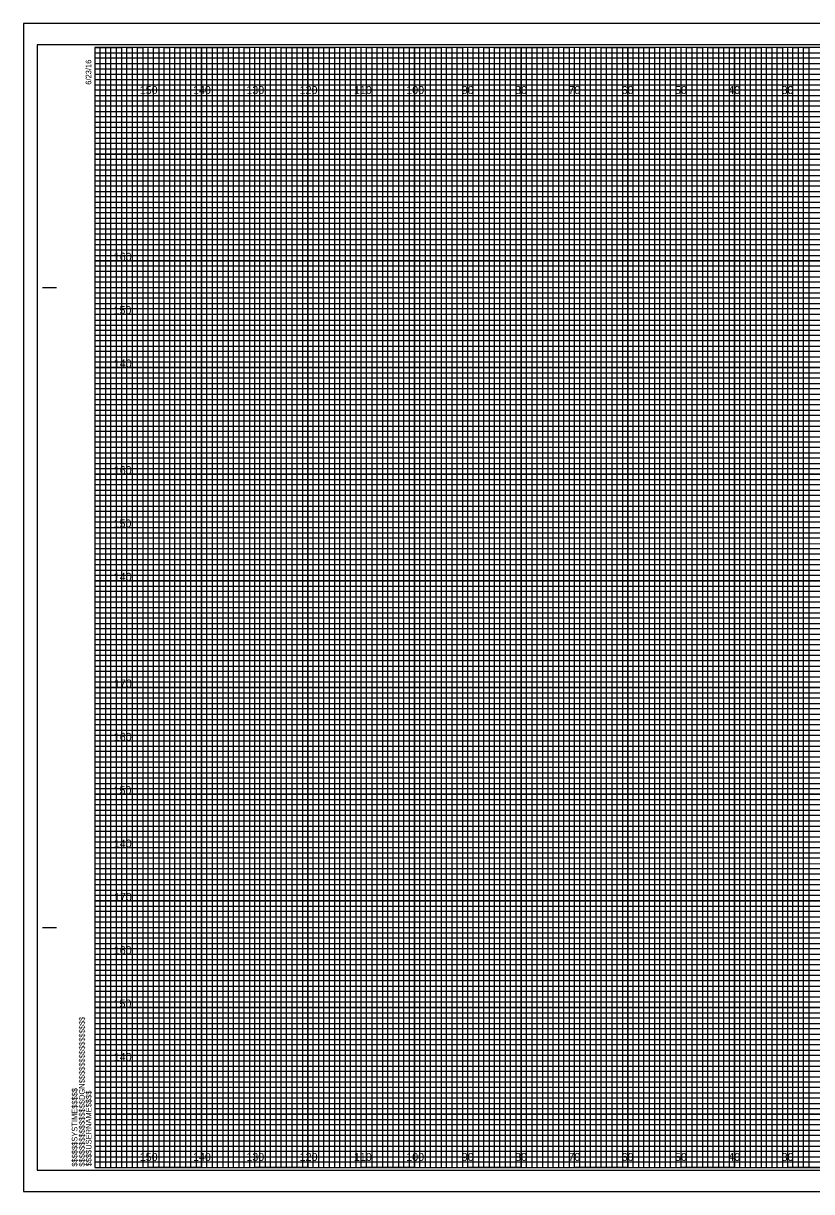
# Model space of a CAD drawing. Extents: x -13 to 323, y -5 to 434.
# Drawn here: x -13.4 to 134.5, y -4.5 to 214.5 of the extents above; entities that cross this region are included whole.
import ezdxf

# ---------------------------------------------------------------- set-up
doc = ezdxf.new("R2010")
doc.units = 0
for name, color, linetype in [('Exist Cross Section Cell', 7, 'Continuous'), ('Exist XS Center Line Elevation Label', 7, 'Continuous'), ('Exist XS Ground Line', 7, 'Continuous'), ('Prop CMT Pvmt Course 1', 7, 'Continuous'), ('Prop CMT Pvmt Course 3', 7, 'Continuous'), ('Prop CMT Pvmt Surface', 7, 'Continuous'), ('Prop CMT Pvmt Surface Shoulder', 7, 'Continuous'), ('Prop CMT Shld Paved Course 1', 7, 'Continuous'), ('Prop CMT Shld Paved Course 2', 7, 'Continuous'), ('Prop CMT Shld Paved Course 3', 7, 'Continuous'), ('Prop CMT Subgrade Earthwork', 7, 'Continuous')]:
    doc.layers.add(name, color=color, linetype=linetype)

msp = doc.modelspace()

# ---------------------------------------------------------------- linework, layer by layer
at = {"layer": 'Exist XS Center Line Elevation Label'}
for points in [[(0, 210), (5, 210), (5, 0), (15, 0), (15, 210), (25, 210), (25, 0), (35, 0), (35, 210), (45, 210), (45, 0), (55, 0), (55, 210), (65, 210), (65, 0), (75, 0), (75, 210), (85, 210), (85, 0), (95, 0), (95, 210), (105, 210), (105, 0), (115, 0), (115, 210), (125, 210), (125, 0), (135, 0)], [(0, 205), (275, 205)], [(0, 185), (320, 185), (320, 195), (0, 195)], [(0, 165), (320, 165), (320, 175), (0, 175)], [(0, 145), (320, 145), (320, 155), (0, 155)], [(0, 125), (320, 125), (320, 135), (0, 135)], [(0, 105), (320, 105), (320, 115), (0, 115)], [(0, 85), (320, 85), (320, 95), (0, 95)], [(0, 65), (320, 65), (320, 75), (0, 75)], [(0, 45), (320, 45), (320, 55), (0, 55)], [(0, 25), (320, 25), (320, 35), (0, 35)], [(0, 5), (320, 5), (320, 15), (0, 15)]]:
    msp.add_lwpolyline(points, dxfattribs=at)
at = {"layer": 'Exist XS Ground Line'}
for p, q in [((10, 210), (0, 210)), ((10, 0), (10, 210)), ((30, 210), (20, 210)), ((20, 210), (20, 0)), ((30, 0), (30, 210)), ((50, 210), (40, 210)), ((40, 210), (40, 0)), ((50, 0), (50, 210)), ((70, 210), (60, 210)), ((60, 210), (60, 0)), ((70, 0), (70, 210)), ((90, 210), (80, 210)), ((80, 210), (80, 0)), ((90, 0), (90, 210)), ((110, 210), (100, 210)), ((100, 210), (100, 0)), ((110, 0), (110, 210)), ((130, 210), (120, 210)), ((120, 210), (120, 0)), ((130, 0), (130, 210)), ((20, 0), (10, 0)), ((40, 0), (30, 0)), ((60, 0), (50, 0)), ((80, 0), (70, 0)), ((100, 0), (90, 0)), ((120, 0), (110, 0)), ((140, 0), (130, 0))]:
    msp.add_line(p, q, dxfattribs=at)
for points in [[(0, 200), (320, 200), (320, 190), (0, 190)], [(0, 180), (320, 180), (320, 170), (0, 170)], [(0, 160), (320, 160), (320, 150), (0, 150)], [(0, 140), (320, 140), (320, 130), (0, 130)], [(0, 120), (320, 120), (320, 110), (0, 110)], [(0, 100), (320, 100), (320, 90), (0, 90)], [(0, 80), (320, 80), (320, 70), (0, 70)], [(0, 60), (320, 60), (320, 50), (0, 50)], [(0, 40), (320, 40), (320, 30), (0, 30)], [(0, 20), (320, 20), (320, 10), (0, 10)]]:
    msp.add_lwpolyline(points, dxfattribs=at)
at = {"layer": 'Prop CMT Pvmt Course 3'}
msp.add_lwpolyline([(-13.4, -4.5), (323.3, -4.5), (323.3, 214.5), (-13.4, 214.5)], close=True, dxfattribs=at)
at = {"layer": 'Prop CMT Pvmt Surface'}
for p, q in [((10, 0), (10, 210)), ((20, 0), (20, 210)), ((30, 0), (30, 210)), ((40, 0), (40, 210)), ((50, 0), (50, 210)), ((60, 0), (60, 210)), ((70, 0), (70, 210)), ((80, 0), (80, 210)), ((90, 0), (90, 210)), ((100, 0), (100, 210)), ((110, 0), (110, 210)), ((120, 0), (120, 210)), ((130, 0), (130, 210)), ((0, 200), (320, 200)), ((0, 190), (320, 190)), ((0, 180), (320, 180)), ((0, 170), (320, 170)), ((0, 160), (320, 160)), ((0, 150), (320, 150)), ((0, 140), (320, 140)), ((0, 130), (320, 130)), ((0, 120), (320, 120)), ((0, 110), (320, 110)), ((0, 100), (320, 100)), ((0, 90), (320, 90)), ((0, 80), (320, 80)), ((0, 70), (320, 70)), ((0, 60), (320, 60)), ((0, 50), (320, 50)), ((0, 40), (320, 40)), ((0, 30), (320, 30)), ((0, 20), (320, 20)), ((0, 10), (320, 10))]:
    msp.add_line(p, q, dxfattribs=at)
at = {"layer": 'Prop CMT Pvmt Surface Shoulder'}
for p, q in [((323.3, 214.5), (-13.4, 214.5)), ((-13.4, 214.5), (-13.4, -4.5)), ((-13.4, -4.5), (323.3, -4.5))]:
    msp.add_line(p, q, dxfattribs=at)
at = {"layer": 'Prop CMT Shld Paved Course 1'}
for p, q in [((0, 209), (260, 209)), ((260, 207.98), (0, 207.98)), ((0, 207.98), (0, 207)), ((0, 207), (260, 207)), ((260, 205.89), (0, 205.89)), ((0, 205.89), (0, 204)), ((0, 204), (320, 204))]:
    msp.add_line(p, q, dxfattribs=at)
for points in [[(0, 203), (270, 203), (320, 203), (320, 202), (0, 202)], [(0, 201), (320, 201), (320, 199), (0, 199)], [(0, 198), (320, 198), (320, 197), (0, 196.98)], [(0, 196), (320, 196), (320, 194), (0, 194)], [(0, 193), (320, 193), (320, 192), (0, 192)], [(0, 191), (320, 191), (320, 189), (0, 189)], [(0, 188), (320, 188), (320, 187), (0, 187)], [(0, 186), (320, 186), (320, 184), (0, 184)], [(0, 183), (320, 183), (320, 182), (0, 182)], [(0, 181), (320, 181), (320, 179), (0, 179)], [(0, 178), (320, 178), (320, 177), (0, 177)], [(0, 176), (320, 176), (320, 173.95), (320, 173), (320, 172), (0, 172)], [(0, 174), (320, 174), (320, 173), (0, 173)], [(0, 171), (320, 171), (320, 169), (0, 169.03)], [(0, 169.03), (320, 169), (320, 168), (0, 168)], [(0, 167), (320, 167), (320, 166), (0, 166)], [(0, 164), (320, 164), (320, 163), (0, 163)], [(0, 162), (320, 162), (320, 161), (0, 161)], [(-0.07, 158.89), (320, 158.89), (320, 157.88), (-0.07, 157.88)], [(0, 157), (320, 157), (320, 156), (0, 156)], [(0, 154), (320, 154), (320, 153), (0, 153)], [(0, 152), (320, 152), (320, 151), (0, 151)], [(0, 149), (320, 149), (320, 148), (0, 148)], [(0, 147), (320, 147), (320, 146), (0, 146)], [(0, 144), (320, 144), (320, 143), (0, 143)], [(0, 142), (320, 142), (320, 141), (0, 141)], [(0, 139), (320, 139), (319.99, 137.98), (0, 138)], [(0, 137), (320, 137), (320, 136), (0, 136)], [(0, 134), (320, 134), (320, 133), (0, 133)], [(0, 132), (320, 132), (320, 131), (0, 131)], [(0, 129), (320, 129), (320, 128), (0, 128)], [(0, 127), (320, 127), (320, 126), (0, 126)], [(0, 124), (320, 124), (320, 123), (0, 123)], [(0, 122), (320, 122), (320, 121), (0, 121)], [(0, 119), (320, 119), (320, 118), (0, 118)], [(0, 116.99), (320.07, 116.91), (320, 116), (0, 116)], [(0, 114), (320, 114), (320, 113), (0, 113)], [(0, 112), (320, 112), (320, 111), (0, 111)], [(0, 109), (320, 109), (320, 108), (0, 108)], [(0, 107), (320, 107), (320, 106), (0, 106)], [(0, 104), (320, 104), (320, 103), (0, 103)], [(0, 102), (320, 102), (320, 101), (0, 101)], [(0, 99), (320, 99), (320, 98), (0, 98)], [(0, 97), (320, 97), (320, 96), (0, 96)], [(0, 94), (320, 94), (320, 93), (0, 93)], [(0, 92), (320, 92), (320, 91), (0, 91)], [(0, 89), (320, 89), (320, 88), (0, 88)], [(0, 87), (320, 87), (320, 86), (0, 86)], [(0, 84), (320, 84), (320, 83), (0, 83)], [(0, 82), (320, 82), (320, 81), (0, 81)], [(0, 79), (320, 79), (319.99, 77.98), (0, 78)], [(0, 77), (320, 77), (320, 76), (0, 76)], [(0, 74), (320, 74), (320, 73), (0, 73)], [(0, 72), (320, 72), (320, 71), (0, 71)], [(0, 69), (320, 69), (320, 68), (0, 68)], [(0, 67), (320, 67), (320, 66), (0, 66)], [(0, 64), (320, 64), (320, 63), (0, 63)], [(0, 62), (320, 62), (320, 61), (0, 61)], [(0, 59), (320, 59), (320, 58), (0, 58)], [(0, 56.99), (320.07, 56.91), (320, 56), (0, 56)], [(0, 54), (320, 54), (320, 53), (0, 53)], [(0, 52), (320, 52), (320, 51), (0, 51)], [(0, 49), (320, 49), (320, 48), (0, 48)], [(0, 47), (320, 47), (320, 46), (0, 46)], [(0, 44), (320, 44), (320, 43), (0, 43)], [(0, 42), (320, 42), (320, 41), (0, 41)], [(0, 39), (320, 39), (320, 38), (0, 38)], [(0, 37), (320, 37), (320, 36), (0, 36)], [(0, 34), (320, 34), (320, 33), (0, 33)], [(0, 32), (320, 32), (320, 31), (0, 31)], [(0, 29), (320, 29), (320, 28), (0, 28)], [(0, 27), (320, 27), (320, 26), (0, 26)], [(0, 24), (320, 24), (320, 23), (0, 23)], [(0, 22), (320, 22), (320, 21), (0, 21)], [(0, 19), (320, 19), (320, 18), (0, 18)], [(0, 17), (320, 17), (320, 16), (0, 16)], [(0, 14), (320, 14), (320, 13), (0, 13)], [(0, 12), (320, 12), (320, 11), (0, 11)], [(0, 9), (320, 9), (320, 8), (0, 8)], [(0, 7), (320, 7), (320, 6), (0, 6)], [(0, 4), (320, 4), (320, 3), (0, 3)], [(0, 2), (320, 2), (320, 1), (0, 1)]]:
    msp.add_lwpolyline(points, dxfattribs=at)
at = {"layer": 'Prop CMT Shld Paved Course 2'}
for p, q in [((-9.8, 165), (-7.3, 165)), ((-9.7, 165), (-7.2, 165)), ((-9.8, 45), (-7.3, 45)), ((-9.7, 45), (-7.2, 45)), ((0, 0), (0, 0)), ((0, 0), (0, 0)), ((0, 0), (0, 0)), ((0, 0), (0, 0)), ((0, 0), (0, 0)), ((0, 0), (0, 0)), ((0, 0), (0, 0))]:
    msp.add_line(p, q, dxfattribs=at)
msp.add_lwpolyline([(320, 210), (0, 210), (0, 0), (320, 0)], close=True, dxfattribs=at)
at = {"layer": 'Prop CMT Shld Paved Course 3'}
for points in [[(0, 0), (1, 0), (1, 210), (2, 210), (2, 0)], [(2, 0), (3, 0), (3, 210), (4, 210), (4, 0)], [(5, 0), (6, 0), (6, 210), (7, 210), (7, 0)], [(7, 0), (8, 0), (8, 210), (9, 210), (9, 0)], [(10, 0), (11, 0), (11, 210), (12, 210), (12, 0)], [(12, 0), (13, 0), (13, 210), (14, 210), (14, 0)], [(15, 0), (16, 0), (16, 210), (17, 210), (17, 0)], [(17, 0), (18, 0), (18, 210), (19, 210), (19, 0)], [(20, 0), (21, 0), (21, 210), (22, 210), (22, 0)], [(22, 0), (23, 0), (23, 210), (24, 210), (24, 0)], [(25, 0), (26, 0), (26, 210), (27, 210), (27, 0)], [(27, 0), (28, 0), (28, 210), (29, 210), (29, 0)], [(30, 0), (31, 0), (31, 210), (32, 210), (32, 0)], [(32, 0), (33, 0), (33, 210), (34, 210), (34, 0)], [(35, 0), (36, 0), (36, 210), (37, 210), (37, 0)], [(37, 0), (38, 0), (38, 210), (39, 210), (39, 0)], [(40, 0), (41, 0), (41, 210), (42, 210), (42, 0)], [(42, 0), (43, 0), (43, 210), (44, 210), (44, 0)], [(45, 0), (46, 0), (46, 210), (47, 210), (47, 0)], [(47, 0), (48, 0), (48, 210), (49, 210), (49, 0)], [(50, 0), (51, 0), (51, 210), (52, 210), (52, 0)], [(52, 0), (53, 0), (53, 210), (54, 210), (54, 0)], [(55, 0), (56, 0), (56, 210), (57, 210), (57, 0)], [(57, 0), (58, 0), (58, 210), (59, 210), (59, 0)], [(60, 0), (61, 0), (61, 210), (62, 210), (62, 0)], [(62, 0), (63, 0), (63, 210), (64, 210), (64, 0)], [(65, 0), (66, 0), (66, 210), (67, 210), (67, 0)], [(67, 0), (68, 0), (68, 210), (69, 210), (69, 0)], [(70, 0), (71, 0), (71, 210), (72, 210), (72, 0)], [(72, 0), (73, 0), (73, 210), (74, 210), (74, 0)], [(75, 0), (76, 0), (76, 210), (77, 210), (77, 0)], [(77, 0), (78, 0), (78, 210), (79, 210), (79, 0)], [(80, 0), (81, 0), (81, 210), (82, 210), (82, 0)], [(82, 0), (83, 0), (83, 210), (84, 210), (84, 0)], [(85, 0), (86, 0), (86, 210), (87, 210), (87, 0)], [(87, 0), (88, 0), (88, 210), (89, 210), (89, 0)], [(90, 0), (91, 0), (91, 210), (92, 210), (92, 0)], [(92, 0), (93, 0), (93, 210), (94, 210), (94, 0)], [(95, 0), (96, 0), (96, 210), (97, 210), (97, 0)], [(97, 0), (98, 0), (98, 210), (99, 210), (99, 0)], [(100, 0), (101, 0), (101, 210), (102, 210), (102, 0)], [(102, 0), (103, 0), (103, 210), (104, 210), (104, 0)], [(105, 0), (106, 0), (106, 210), (107, 210), (107, 0)], [(107, 0), (108, 0), (108, 210), (109, 210), (109, 0)], [(110, 0), (111, 0), (111, 210), (112, 210), (112, 0)], [(112, 0), (113, 0), (113, 210), (114, 210), (114, 0)], [(115, 0), (116, 0), (116, 210), (117, 210), (117, 0)], [(117, 0), (118, 0), (118, 210), (119, 210), (119, 0)], [(120, 0), (121, 0), (121, 210), (122, 210), (122, 0)], [(122, 0), (123, 0), (123, 210), (124, 210), (124, 0)], [(125, 0), (126, 0), (126, 210), (127, 210), (127, 0)], [(127, 0), (128, 0), (128, 210), (129, 210), (129, 0)], [(130, 0), (131, 0), (131, 210), (132, 210), (132, 0)], [(132, 0), (133, 0), (133, 210), (134, 210), (134, 0)]]:
    msp.add_lwpolyline(points, dxfattribs=at)
at = {"layer": 'Prop CMT Subgrade Earthwork'}
msp.add_lwpolyline([(-10.8, -0.5), (322.4, -0.5), (322.4, 210.5), (-10.8, 210.5)], close=True, dxfattribs=at)

# ---------------------------------------------------------------- texts
at = {"layer": 'Exist Cross Section Cell'}
for s, p in [('150', (8.44, 201.25)), ('140', (18.44, 201.25)), ('130', (28.44, 201.25)), ('120', (38.44, 201.25)), ('110', (48.62, 201.25)), ('100', (58.44, 201.25)), ('90', (68.86, 201.25)), ('80', (78.86, 201.25)), ('70', (88.86, 201.25)), ('60', (98.86, 201.25)), ('50', (108.86, 201.25)), ('40', (118.86, 201.25)), ('30', (128.86, 201.25)), ('150', (8.44, 1.25)), ('140', (18.44, 1.25)), ('130', (28.44, 1.25)), ('120', (38.44, 1.25)), ('110', (48.62, 1.25)), ('100', (58.44, 1.25)), ('90', (68.86, 1.25)), ('80', (78.86, 1.25)), ('70', (88.86, 1.25)), ('60', (98.86, 1.25)), ('50', (108.86, 1.25)), ('40', (118.86, 1.25)), ('30', (128.86, 1.25))]:
    msp.add_text(s, height=1.5, dxfattribs=at).set_placement(p)
at = {"layer": 'Prop CMT Pvmt Course 1'}
for s, p in [('160', (3.57, 170)), ('150', (3.52, 160)), ('140', (3.57, 150)), ('160', (3.57, 130)), ('150', (3.52, 120)), ('140', (3.57, 110)), ('170', (3.61, 90)), ('160', (3.57, 80)), ('150', (3.52, 70)), ('140', (3.57, 60)), ('170', (3.61, 50)), ('160', (3.57, 40)), ('150', (3.52, 30)), ('140', (3.57, 20))]:
    msp.add_text(s, height=1.5, dxfattribs=at).set_placement(p)
at = {"layer": 'Prop CMT Shld Paved Course 2'}
for s, p in [('6/23/16', (-0.65, 203)), ('$$$$$$$$$$$$$$$$DGN$$$$$$$$$$$$$$$$', (-1.88, 0.18)), ('$$$$$$SYSTIME$$$$$', (-3.26, 0.18)), ('$$$$USERNAME$$$$', (-0.62, 0.23))]:
    msp.add_text(s, height=1.05, rotation=90, dxfattribs=at).set_placement(p)

doc.saveas('drawing.dxf')
